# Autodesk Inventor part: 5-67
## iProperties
Company: HERDT-Verlag
Shininess: 64.0
Length Units: 11269
Angle Units: 11279
Time Units: 11290
Mass Units: 11283
Length Display Precision: 3
Angle Display Precision: 2
Compacted: True
Part Number: 5-67
Document SubType Name: Modeling
Created: 2006-01
Designer: Eichenseer
Checked By: G. Lehmann
Engr Approved By: M. Grouls
Project: Inventor 11 - Grundkurs
Density: 0.0
Volumn: 0.0
Area: 0.0
PropertySet Name: Model Information
Control State: 0
Master: False
Checked Out: False
Author: P. Tropf
Subject: Inventor 10 - Grundkurs
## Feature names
1. Revolution1
